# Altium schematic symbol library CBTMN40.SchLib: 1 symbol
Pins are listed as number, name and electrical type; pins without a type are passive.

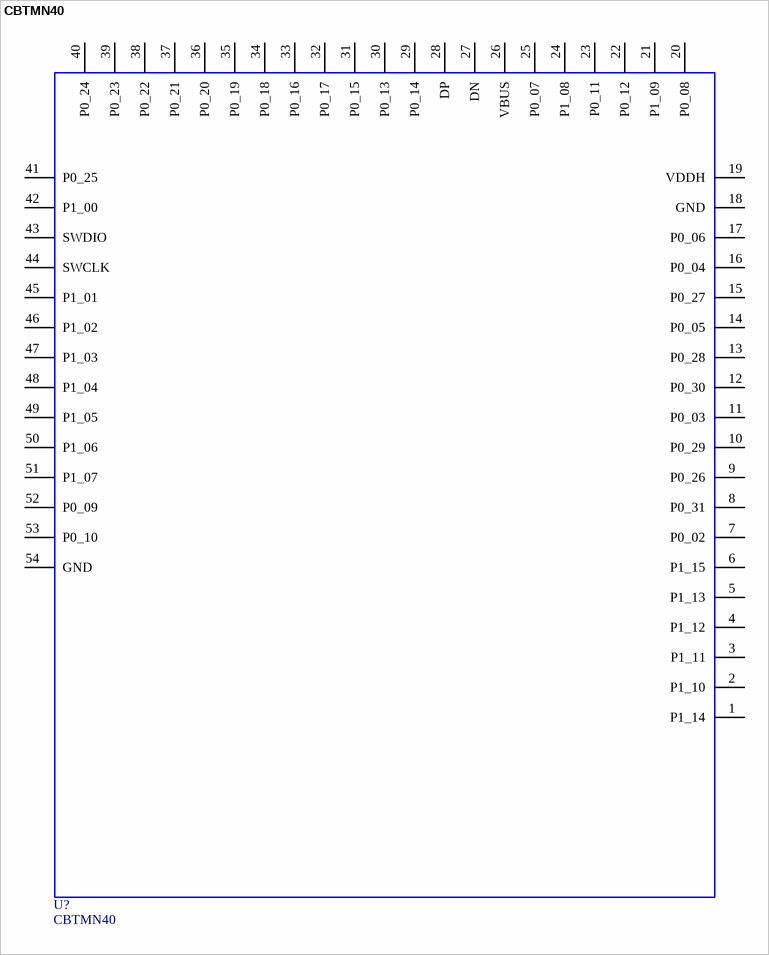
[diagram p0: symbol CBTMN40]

## CBTMN40
designator U?
module CBTMN40
footprint CBTMN401
pins: 1 P1_14, 2 P1_10, 3 P1_11, 4 P1_12, 5 P1_13, 6 P1_15, 7 P0_02, 8 P0_31, 9 P0_26, 10 P0_29, 11 P0_03, 12 P0_30, 13 P0_28, 14 P0_05, 15 P0_27, 16 P0_04, 17 P0_06, 18 GND, 19 VDDH, 20 P0_08, 21 P1_09, 22 P0_12, 23 P0_11, 24 P1_08, 25 P0_07, 26 VBUS, 27 DN, 28 DP, 29 P0_14, 30 P0_13, 31 P0_15, 32 P0_17, 33 P0_16, 34 P0_18, 35 P0_19, 36 P0_20, 37 P0_21, 38 P0_22, 39 P0_23, 40 P0_24, 41 P0_25, 42 P1_00, 43 SWDIO, 44 SWCLK, 45 P1_01, 46 P1_02, 47 P1_03, 48 P1_04, 49 P1_05, 50 P1_06, 51 P1_07, 52 P0_09, 53 P0_10, 54 GND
